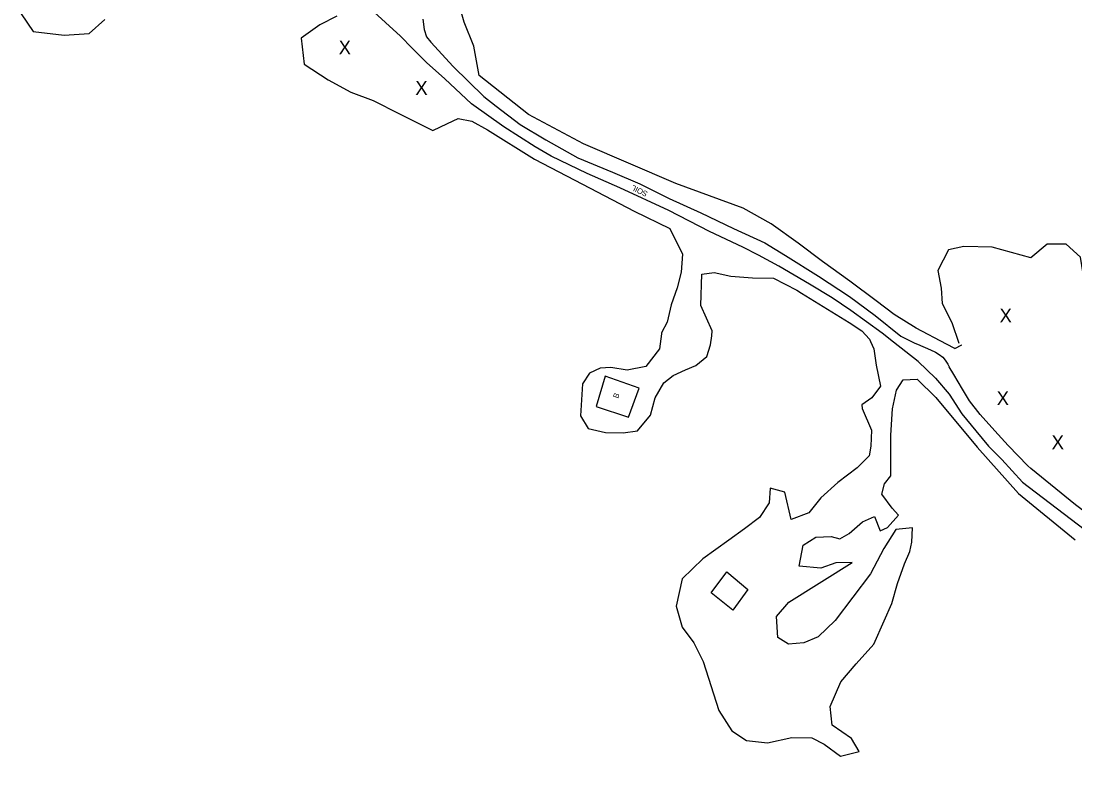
# Model space of a CAD drawing. Extents: x 2030130 to 2036320, y 723205 to 762423.
# Drawn here: x 2031191 to 2031951, y 748762 to 749317 of the extents above; entities that cross this region are included whole.
import ezdxf

# ---------------------------------------------------------------- set-up
doc = ezdxf.new("R2010")
doc.units = 0
for name, color, linetype in [('Draft_Station Labels Major', 7, 'Continuous'), ('Draft_Station Tics Major', 7, 'Continuous'), ('Exist Terrain Model Ground Surface', 7, 'Continuous'), ('Old_Level_23', 7, 'Continuous'), ('Old_Level_28', 7, 'Continuous')]:
    doc.layers.add(name, color=color, linetype=linetype)

msp = doc.modelspace()

# ---------------------------------------------------------------- linework, layer by layer
at = {"layer": 'Draft_Station Labels Major'}
for points in [[(2031819.87, 749085.14), (2031811.68, 749091.63), (2031789.08, 749107.93), (2031775.58, 749117.17), (2031759.17, 749127), (2031736.96, 749139.93), (2031722.44, 749147.98), (2031711.07, 749153.72), (2031687.08, 749165.05), (2031657.66, 749180.28), (2031622.43, 749196.48), (2031598.76, 749206.96), (2031572.9, 749219.39), (2031561.4, 749226.09), (2031538.68, 749240.45), (2031515.49, 749257.12), (2031496.22, 749275.06), (2031483.03, 749286.92), (2031472.68, 749297.22), (2031464.21, 749305.84), (2031442.67, 749325.65)], [(2031480.34, 749318.3), (2031481.24, 749310.7), (2031482.85, 749305.44), (2031485.96, 749301.58), (2031502.22, 749284.03), (2031524.4, 749262.51), (2031533.2, 749255.34), (2031550.39, 749242.26), (2031569.07, 749231.24), (2031592.14, 749218.14), (2031617.07, 749207.8), (2031636.91, 749199.53), (2031658.08, 749188.78), (2031680.78, 749178.47), (2031704.38, 749167.31), (2031726.89, 749156.9), (2031741.84, 749147.8), (2031765.65, 749132.89), (2031788, 749118.13), (2031806.66, 749104.41), (2031825.15, 749089.63), (2031835.26, 749084.59)], [(2031837.49, 749071.18), (2031819.87, 749085.14)], [(2031835.26, 749084.59), (2031837.01, 749083.71), (2031846.5, 749079.56), (2031850.02, 749077.93), (2031852.78, 749076.28), (2031855.34, 749074.33), (2031857.14, 749072.26), (2031858.97, 749069.23), (2031860, 749067.33)], [(2031837.49, 749071.18), (2031850.09, 749059.33), (2031859.85, 749047.63), (2031869.19, 749033.42), (2031879.15, 749021.18), (2031888.27, 749010.23), (2031897.83, 749000.63), (2031912.9, 748984.1)], [(2031918.95, 748994.1), (2031916.59, 748995.94), (2031902.47, 749010.73), (2031892.93, 749021.3), (2031882.29, 749033.04), (2031874.7, 749043), (2031869.66, 749051.3), (2031863.25, 749061.77), (2031860, 749067.33)], [(2032063.55, 748882.96), (2032032.77, 748905.25), (2031990.7, 748937.82), (2031950.96, 748967.86), (2031918.95, 748994.1)], [(2031912.9, 748984.1), (2031962.28, 748946.45), (2032010.79, 748909.63), (2032056.64, 748875.92), (2032102.33, 748840.62), (2032204.54, 748762.2)]]:
    msp.add_lwpolyline(points, dxfattribs=at)
at = {"layer": 'Draft_Station Tics Major'}
for points in [[(2031858.12, 749083.76), (2031836.21, 749095.25), (2031820.28, 749105.18), (2031807.25, 749115.01), (2031788.29, 749129.29), (2031768.57, 749143.35), (2031751, 749156.71), (2031731.47, 749170.59), (2031711.45, 749181.94), (2031662.68, 749199.75), (2031596.21, 749228.22), (2031556.6, 749249.4), (2031521.01, 749277.64), (2031517.09, 749298.74), (2031510.01, 749316.09), (2031507.19, 749326.23)], [(2031190.52, 749322.01), (2031199.2, 749309.35), (2031221.67, 749306.56), (2031239.57, 749307.87), (2031251.03, 749317.87)], [(2031418.23, 749320.44), (2031406.07, 749314.09), (2031392.48, 749304.41), (2031394.59, 749285.76), (2031412.1, 749274.53), (2031428.39, 749265.57), (2031444.39, 749259.49), (2031463.4, 749249.84), (2031487.49, 749237.84), (2031498.14, 749242.99), (2031505.75, 749246.5), (2031515.65, 749244.68), (2031527.03, 749238.27), (2031560.86, 749217.11), (2031595.56, 749199.07), (2031632.8, 749179.75), (2031658.46, 749167.21), (2031667.7, 749148.78), (2031666.55, 749135.62), (2031663.81, 749124.35), (2031659.36, 749112.06), (2031656.65, 749099.63), (2031652.44, 749091.98), (2031652.34, 749091.18)], [(2031990.25, 749055), (2031984.64, 749068.24), (2031984.13, 749085.55), (2031982.61, 749099.29), (2031969.87, 749116.09), (2031956.63, 749134.41), (2031954.59, 749146.63), (2031944.41, 749155.79), (2031930.66, 749155.79), (2031918.94, 749146.12), (2031890.93, 749153.75), (2031870.56, 749154.26), (2031859.36, 749151.72), (2031851.72, 749136.96), (2031854.26, 749124.23), (2031854.77, 749113.03), (2031861.9, 749099.29), (2031866.99, 749084.53), (2031866.93, 749084.44)], [(2031688.65, 749089.87), (2031689.06, 749093.28), (2031680.79, 749111.55), (2031681.45, 749134.15), (2031690.48, 749135.39), (2031702.52, 749132.86), (2031718, 749131.59), (2031733.25, 749131.28), (2031750.1, 749122.73), (2031753.48, 749120.48)], [(2031753.48, 749120.48), (2031787.77, 749099.47), (2031796.86, 749093.36), (2031802.45, 749087.34), (2031803.18, 749085.74)], [(2031652.34, 749091.18), (2031650.95, 749080.31)], [(2031650.95, 749080.31), (2031641.04, 749067.55), (2031627.66, 749065.07), (2031615.81, 749066.96), (2031608.29, 749066.54), (2031600.61, 749062.77), (2031595.58, 749055.21), (2031594.02, 749032.12), (2031599.64, 749022.84), (2031612.04, 749020.07), (2031624.78, 749019.71), (2031635.02, 749021.22), (2031644.42, 749032.52), (2031647.94, 749045.06), (2031654.14, 749055.76), (2031660.94, 749061.11), (2031669.72, 749065.28), (2031677.13, 749068.41), (2031685.11, 749074.76), (2031687.84, 749083.18)], [(2031687.84, 749083.18), (2031688.65, 749089.87)], [(2031803.18, 749085.74), (2031805.56, 749080.48), (2031807.27, 749068.72)], [(2031864.05, 749080.66), (2031858.12, 749083.76)], [(2031864.05, 749080.66), (2031868.99, 749083.31), (2031868.97, 749083.37)], [(2031864.1, 749080.67), (2031864.02, 749080.56)], [(2031807.27, 749068.72), (2031810.29, 749053.5), (2031804.27, 749044.97), (2031796.99, 749040.11), (2031797.29, 749037.44), (2031803.91, 749021.71), (2031803.34, 749010.11), (2031802.3, 749003.1), (2031793.58, 748994.46), (2031779.53, 748984.06), (2031767.35, 748973.02), (2031758.67, 748962.06), (2031745.94, 748957.16), (2031741.47, 748976.99), (2031730.8, 748979.88), (2031730.05, 748969.22), (2031723.22, 748958.79), (2031712.28, 748950.52), (2031701.12, 748942.41), (2031682.18, 748928.95), (2031667.33, 748914.5), (2031663, 748894.79), (2031667.37, 748879.62), (2031675.71, 748868.31), (2031682.48, 748854.95), (2031693.75, 748819.43), (2031703.29, 748804.83), (2031713.75, 748797.81), (2031728.87, 748796.13), (2031746.48, 748799.99), (2031760.94, 748799.75), (2031769.78, 748795.16), (2031781.5, 748786.61), (2031794.93, 748789.89), (2031789.46, 748799.39), (2031775.61, 748808.91), (2031774.1, 748822.27), (2031781.9, 748840.09), (2031792.94, 748853.05), (2031805.5, 748867.27), (2031813.1, 748884.08), (2031818.54, 748896.78), (2031822.68, 748911.19), (2031827.65, 748925.37), (2031831.46, 748934.26), (2031832.94, 748940.97), (2031833.38, 748951.18), (2031821.53, 748949.95), (2031812.73, 748936.43), (2031803.27, 748918.11), (2031777.78, 748884.34), (2031765.55, 748872.52), (2031755.01, 748868.42), (2031744.1, 748867.37), (2031736.38, 748872.17), (2031735.32, 748887.37), (2031744.33, 748897.62), (2031789.86, 748926.34), (2031778.24, 748925.94), (2031767.25, 748922.14), (2031751.79, 748923.56), (2031754.63, 748938.7), (2031763.69, 748944.48), (2031774.71, 748944.96), (2031781.04, 748943.41), (2031787.74, 748947.19), (2031797.48, 748955.62), (2031806.13, 748959.37), (2031810.2, 748949.02), (2031815.38, 748951.54), (2031823.29, 748960.42), (2031818.85, 748965.44), (2031811.32, 748975.54), (2031813.26, 748982.91), (2031817.81, 748988.83), (2031817.84, 749018.07), (2031819.16, 749037.21), (2031821.94, 749050.59), (2031826.81, 749057.93), (2031836.82, 749058.62), (2031850.2, 749045.32), (2031880.07, 749009.35), (2031910.02, 748976.13), (2031950.93, 748942.61)]]:
    msp.add_lwpolyline(points, dxfattribs=at)
at = {"layer": 'Exist Terrain Model Ground Surface'}
for points in [[(2031636.4, 749052.03), (2031611.92, 749060.76), (2031605.23, 749038.88), (2031628.55, 749031.2)], [(2031714.76, 748906.87), (2031703.92, 748891.8), (2031688.34, 748904.3), (2031699.56, 748919.44)]]:
    msp.add_lwpolyline(points, close=True, dxfattribs=at)

# ---------------------------------------------------------------- texts
at = {"layer": 'Draft_Station Tics Major'}
for p in [(2031419.57, 749292.79), (2031474.86, 749263.6), (2031896.27, 749099.41), (2031894.19, 749039.77), (2031933.81, 749007.96)]:
    msp.add_text('X', height=10, dxfattribs=at).set_placement(p)
at = {"layer": 'Old_Level_23'}
msp.add_text('SOIL', height=4, rotation=154.81129, dxfattribs=at).set_placement((2031642.95, 749193.55))
at = {"layer": 'Old_Level_28'}
msp.add_text('B', height=4, rotation=70.64408, dxfattribs=at).set_placement((2031621.12, 749044.34))

doc.saveas('drawing.dxf')
